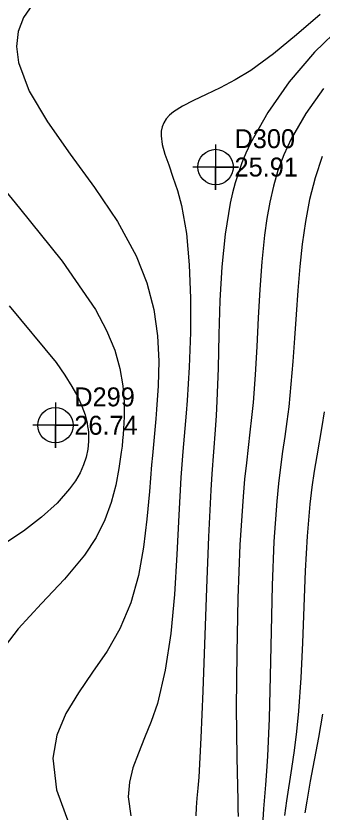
# Model space of a CAD drawing. Extents: x 2356077 to 2359823, y 225951 to 227822.
# Drawn here: x 2356233.7 to 2356274.1, y 227296.2 to 227401.4 of the extents above; entities that cross this region are included whole.
import ezdxf

# ---------------------------------------------------------------- set-up
doc = ezdxf.new("R2010")
doc.units = 0
for name, color, linetype in [('DTM Contours Major', 7, 'Continuous'), ('DTM Contours Minor', 7, 'Continuous'), ('Exist DTM Regular Point CELL', 7, 'Continuous'), ('Exist DTM Regular Point Cogo Elevation', 7, 'Continuous'), ('Exist DTM Regular Point Cogo Number', 7, 'Continuous')]:
    doc.layers.add(name, color=color, linetype=linetype)

msp = doc.modelspace()

# ---------------------------------------------------------------- linework, layer by layer
at = {"layer": 'DTM Contours Major'}
for points in [[(2356273.89, 227401.53), (2356270.76, 227398.86), (2356267.71, 227396.34), (2356264.73, 227394.16), (2356262.66, 227392.91), (2356260.67, 227391.87), (2356258.81, 227390.98), (2356257.12, 227390.19), (2356255.66, 227389.44), (2356254.48, 227388.68), (2356253.95, 227388.24), (2356253.53, 227387.76), (2356253.21, 227387.26), (2356252.99, 227386.72), (2356252.87, 227386.14), (2356252.85, 227385.51), (2356253.01, 227384.38), (2356253.36, 227383.11), (2356253.86, 227381.68), (2356254.42, 227380.08), (2356255, 227378.31), (2356255.53, 227376.34), (2356256.19, 227372.63), (2356256.58, 227368.49), (2356256.75, 227364.08), (2356256.73, 227359.53), (2356256.56, 227354.99), (2356256.28, 227350.59), (2356256.15, 227348.88), (2356255.74, 227343.85), (2356255.61, 227342.14), (2356255.48, 227340.39), (2356255.2, 227335.45), (2356254.94, 227330.24), (2356254.61, 227324.97), (2356254.12, 227319.8), (2356253.4, 227314.94), (2356252.36, 227310.57), (2356251.55, 227308.19), (2356250.68, 227306.02), (2356249.85, 227304), (2356249.14, 227302.07), (2356248.66, 227300.17), (2356248.5, 227298.25), (2356248.84, 227295.72)], [(2356274.2, 227309.14), (2356273.65, 227306.06), (2356272.56, 227300.29), (2356272.09, 227297.66), (2356271.84, 227296.1)]]:
    msp.add_lwpolyline(points, dxfattribs=at)
at = {"layer": 'DTM Contours Minor'}
for points in [[(2356235.87, 227402.87), (2356234.68, 227401.17), (2356233.96, 227399.32), (2356233.73, 227397.33), (2356233.99, 227395.19), (2356235.43, 227391.43), (2356237.84, 227387.38), (2356240.84, 227383.11), (2356244.04, 227378.69), (2356247.08, 227374.19), (2356249.58, 227369.69), (2356250.99, 227366.1), (2356251.9, 227362.57), (2356252.38, 227359.12), (2356252.55, 227355.76), (2356252.48, 227352.51), (2356252.26, 227349.39), (2356252.16, 227348.17), (2356251.7, 227343.31), (2356251.59, 227342.06), (2356251.31, 227338.57), (2356250.99, 227334.91), (2356250.54, 227331.19), (2356249.85, 227327.47), (2356248.84, 227323.86), (2356247.41, 227320.42), (2356245.72, 227317.49), (2356243.81, 227314.7), (2356241.92, 227311.98), (2356240.27, 227309.23), (2356239.07, 227306.39), (2356238.54, 227303.36), (2356239.05, 227299.16), (2356240.68, 227294.69)], [(2356276.77, 227400.1), (2356273.11, 227396.55), (2356269.79, 227392.66), (2356266.94, 227388.61), (2356264.67, 227384.57), (2356264.06, 227383.25), (2356263.53, 227381.95), (2356263.06, 227380.64), (2356262.65, 227379.33), (2356262.3, 227378), (2356261.99, 227376.64), (2356261.3, 227372.53), (2356260.88, 227368.22), (2356260.63, 227363.77), (2356260.49, 227359.27), (2356260.38, 227354.82), (2356260.21, 227350.48), (2356260.11, 227348.59), (2356259.98, 227346.71), (2356259.56, 227340.87), (2356259.42, 227338.75), (2356259.1, 227332.56), (2356258.84, 227325.81), (2356258.38, 227312.17), (2356258.12, 227306.03), (2356257.82, 227300.84), (2356257.7, 227299.37), (2356257.59, 227298.04), (2356257.5, 227296.83), (2356257.44, 227295.71)], [(2356274.33, 227391.79), (2356271.96, 227388.48), (2356270.02, 227385.11), (2356269.07, 227383.03), (2356268.3, 227380.96), (2356267.69, 227378.88), (2356267.2, 227376.77), (2356266.82, 227374.62), (2356266.52, 227372.42), (2356266.16, 227368.88), (2356265.9, 227365.21), (2356265.7, 227361.47), (2356265.5, 227357.71), (2356265.28, 227353.97), (2356265, 227350.3), (2356264.8, 227348.34), (2356264.59, 227346.39), (2356264.12, 227342.34), (2356263.89, 227340.18), (2356263.68, 227337.89), (2356263.26, 227331.52), (2356262.99, 227324.49), (2356262.84, 227317.2), (2356262.79, 227310.04), (2356262.85, 227303.42), (2356262.98, 227297.73), (2356263.01, 227296.65), (2356263.05, 227295.63)], [(2356228.08, 227383.35), (2356234.16, 227375.98), (2356239.79, 227368.96), (2356244.17, 227362.61), (2356245.66, 227359.8), (2356246.72, 227357.2), (2356247.41, 227354.78), (2356247.81, 227352.53), (2356247.98, 227350.41), (2356247.98, 227348.41), (2356247.95, 227347.62), (2356247.9, 227346.84), (2356247.84, 227346.07), (2356247.77, 227345.3), (2356247.69, 227344.52), (2356247.59, 227343.74), (2356247.29, 227341.59), (2356246.87, 227339.38), (2356246.27, 227337.11), (2356245.42, 227334.8), (2356244.27, 227332.47), (2356242.75, 227330.14), (2356240.1, 227326.99), (2356237.04, 227323.78), (2356233.95, 227320.43), (2356231.2, 227316.85)], [(2356274.14, 227382.79), (2356273.2, 227379.99), (2356272.48, 227377.11), (2356271.93, 227374.19), (2356271.51, 227371.23), (2356271.19, 227368.26), (2356270.92, 227365.09), (2356270.69, 227361.94), (2356270.48, 227358.82), (2356270.26, 227355.74), (2356270.01, 227352.71), (2356269.71, 227349.74), (2356269.46, 227347.79), (2356269.19, 227345.83), (2356268.91, 227343.84), (2356268.63, 227341.77), (2356268.36, 227339.6), (2356268.13, 227337.29), (2356267.76, 227331.96), (2356267.53, 227326.14), (2356267.38, 227320.12), (2356267.26, 227314.17), (2356267.13, 227308.57), (2356266.93, 227303.6), (2356266.8, 227301.64), (2356266.67, 227299.84), (2356266.4, 227296.64), (2356266.29, 227295.19)], [(2356232.76, 227363.06), (2356238.97, 227355.57), (2356240.14, 227353.92), (2356241.08, 227352.42), (2356241.83, 227351.06), (2356242.39, 227349.81), (2356242.8, 227348.66), (2356243.07, 227347.58), (2356243.15, 227347.16), (2356243.21, 227346.75), (2356243.25, 227346.35), (2356243.27, 227345.95), (2356243.27, 227345.56), (2356243.26, 227345.17), (2356243.16, 227344.13), (2356242.95, 227343.1), (2356242.61, 227342.06), (2356242.14, 227341.02), (2356241.53, 227339.97), (2356240.77, 227338.9), (2356239.11, 227337.03), (2356237.05, 227335.15), (2356234.65, 227333.3), (2356231.95, 227331.53)], [(2356274.38, 227349.07), (2356274.08, 227347.15), (2356273.41, 227343.27), (2356273.08, 227341.25), (2356272.77, 227339.12), (2356272.49, 227336.87), (2356272.14, 227332.64), (2356271.9, 227328.08), (2356271.72, 227323.34), (2356271.55, 227318.57), (2356271.33, 227313.93), (2356271.02, 227309.55), (2356270.75, 227306.86), (2356270.42, 227304.35), (2356270.08, 227301.99), (2356269.42, 227297.71), (2356269.14, 227295.75)]]:
    msp.add_lwpolyline(points, dxfattribs=at)
at = {"layer": 'Exist DTM Regular Point CELL'}
for points in [[(2356260.06, 227384.4), (2356260.06, 227378.4), (2356260.06, 227381.4), (2356263.06, 227381.4), (2356257.06, 227381.4)], [(2356238.89, 227350.3), (2356238.89, 227344.3), (2356238.89, 227347.3), (2356241.89, 227347.3), (2356235.89, 227347.3)]]:
    msp.add_lwpolyline(points, dxfattribs=at)
for centre in [(2356260.06, 227381.4), (2356238.89, 227347.3)]:
    msp.add_circle(centre, 2.34, dxfattribs=at)

# ---------------------------------------------------------------- texts
at = {"layer": 'Exist DTM Regular Point Cogo Elevation'}
for s, p in [('25.91', (2356262.56, 227380.15)), ('26.74', (2356241.39, 227346.05))]:
    msp.add_text(s, height=2.5, dxfattribs=at).set_placement(p)
at = {"layer": 'Exist DTM Regular Point Cogo Number'}
for s, p in [('D300', (2356262.56, 227383.9)), ('D299', (2356241.39, 227349.8))]:
    msp.add_text(s, height=2.5, dxfattribs=at).set_placement(p)

doc.saveas('drawing.dxf')
